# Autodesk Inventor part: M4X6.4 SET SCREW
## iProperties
IsCustomPart: 1
Created: 2006-02
Part Number: M4X6.4 SET SCREW
Material: Steel, Mild
Description: Slotted set screws with cup point
Document SubType Name: Modeling
Standard: DIN 438
Designer: Andy Moles
Standards Organization: DIN
Language: en-US
Size Designation: M4x6
Categories: <MemberInstance><Categories><Category DisplayName="Fasteners" InternalName="e4da775c-781d-43d5-af7c-5136215cf5a6" Mnemonic="FSTN"><Category DisplayName="Bolts"
Density: 7.86 g/cm^3
Author: Andy Moles
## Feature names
1. Revolution1
2. Extrusion1
